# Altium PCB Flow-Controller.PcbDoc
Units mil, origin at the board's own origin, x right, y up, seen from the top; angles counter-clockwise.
Board outline 3346.46 x 3543.31 mil, 2 copper layers (Top Layer, Bottom Layer), stack 61.855 mil thick; 107 components, 78 nets, 319 pads, 143 vias.
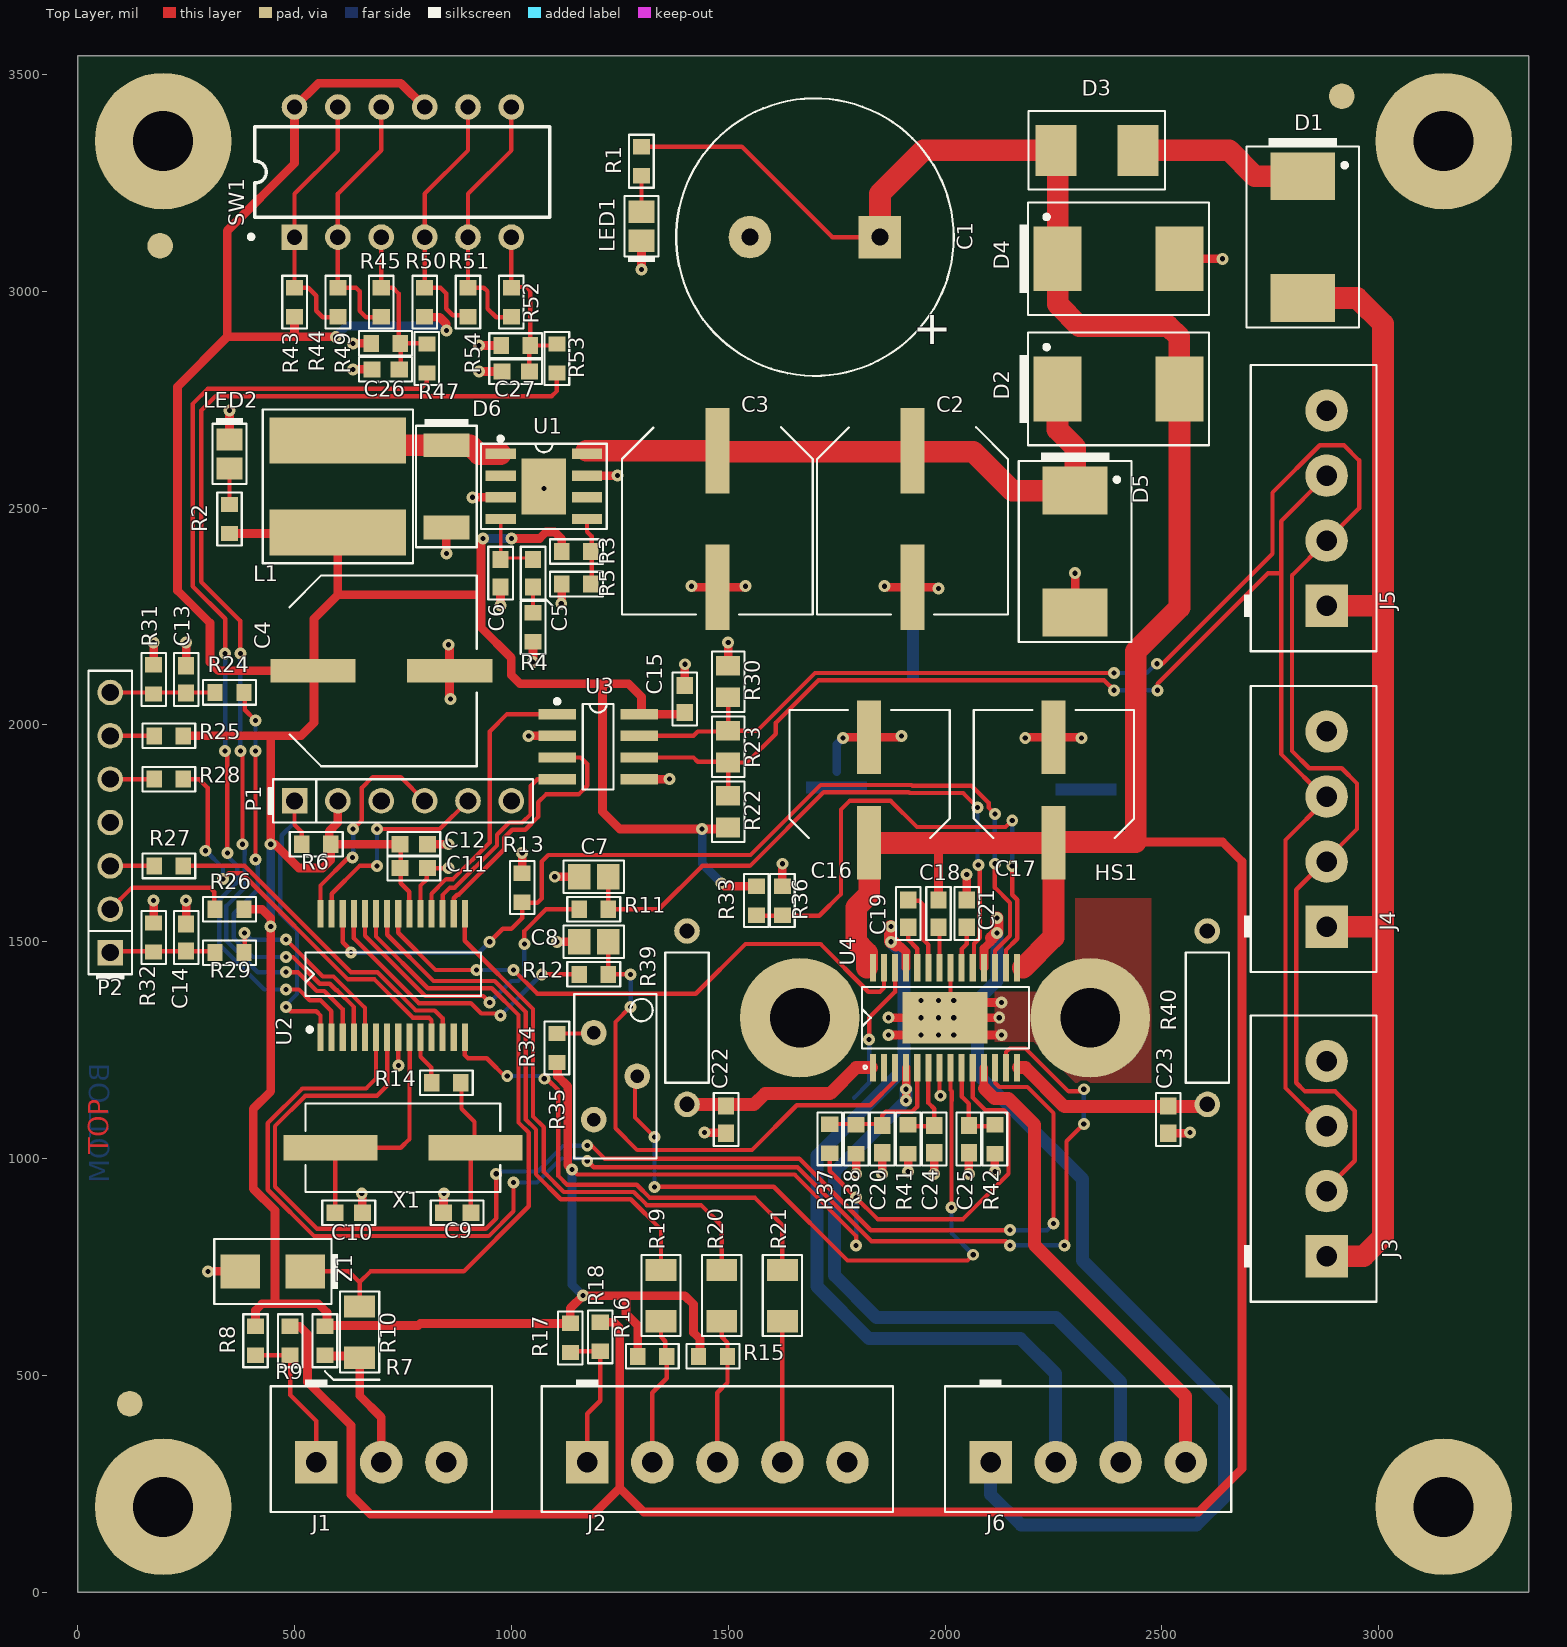
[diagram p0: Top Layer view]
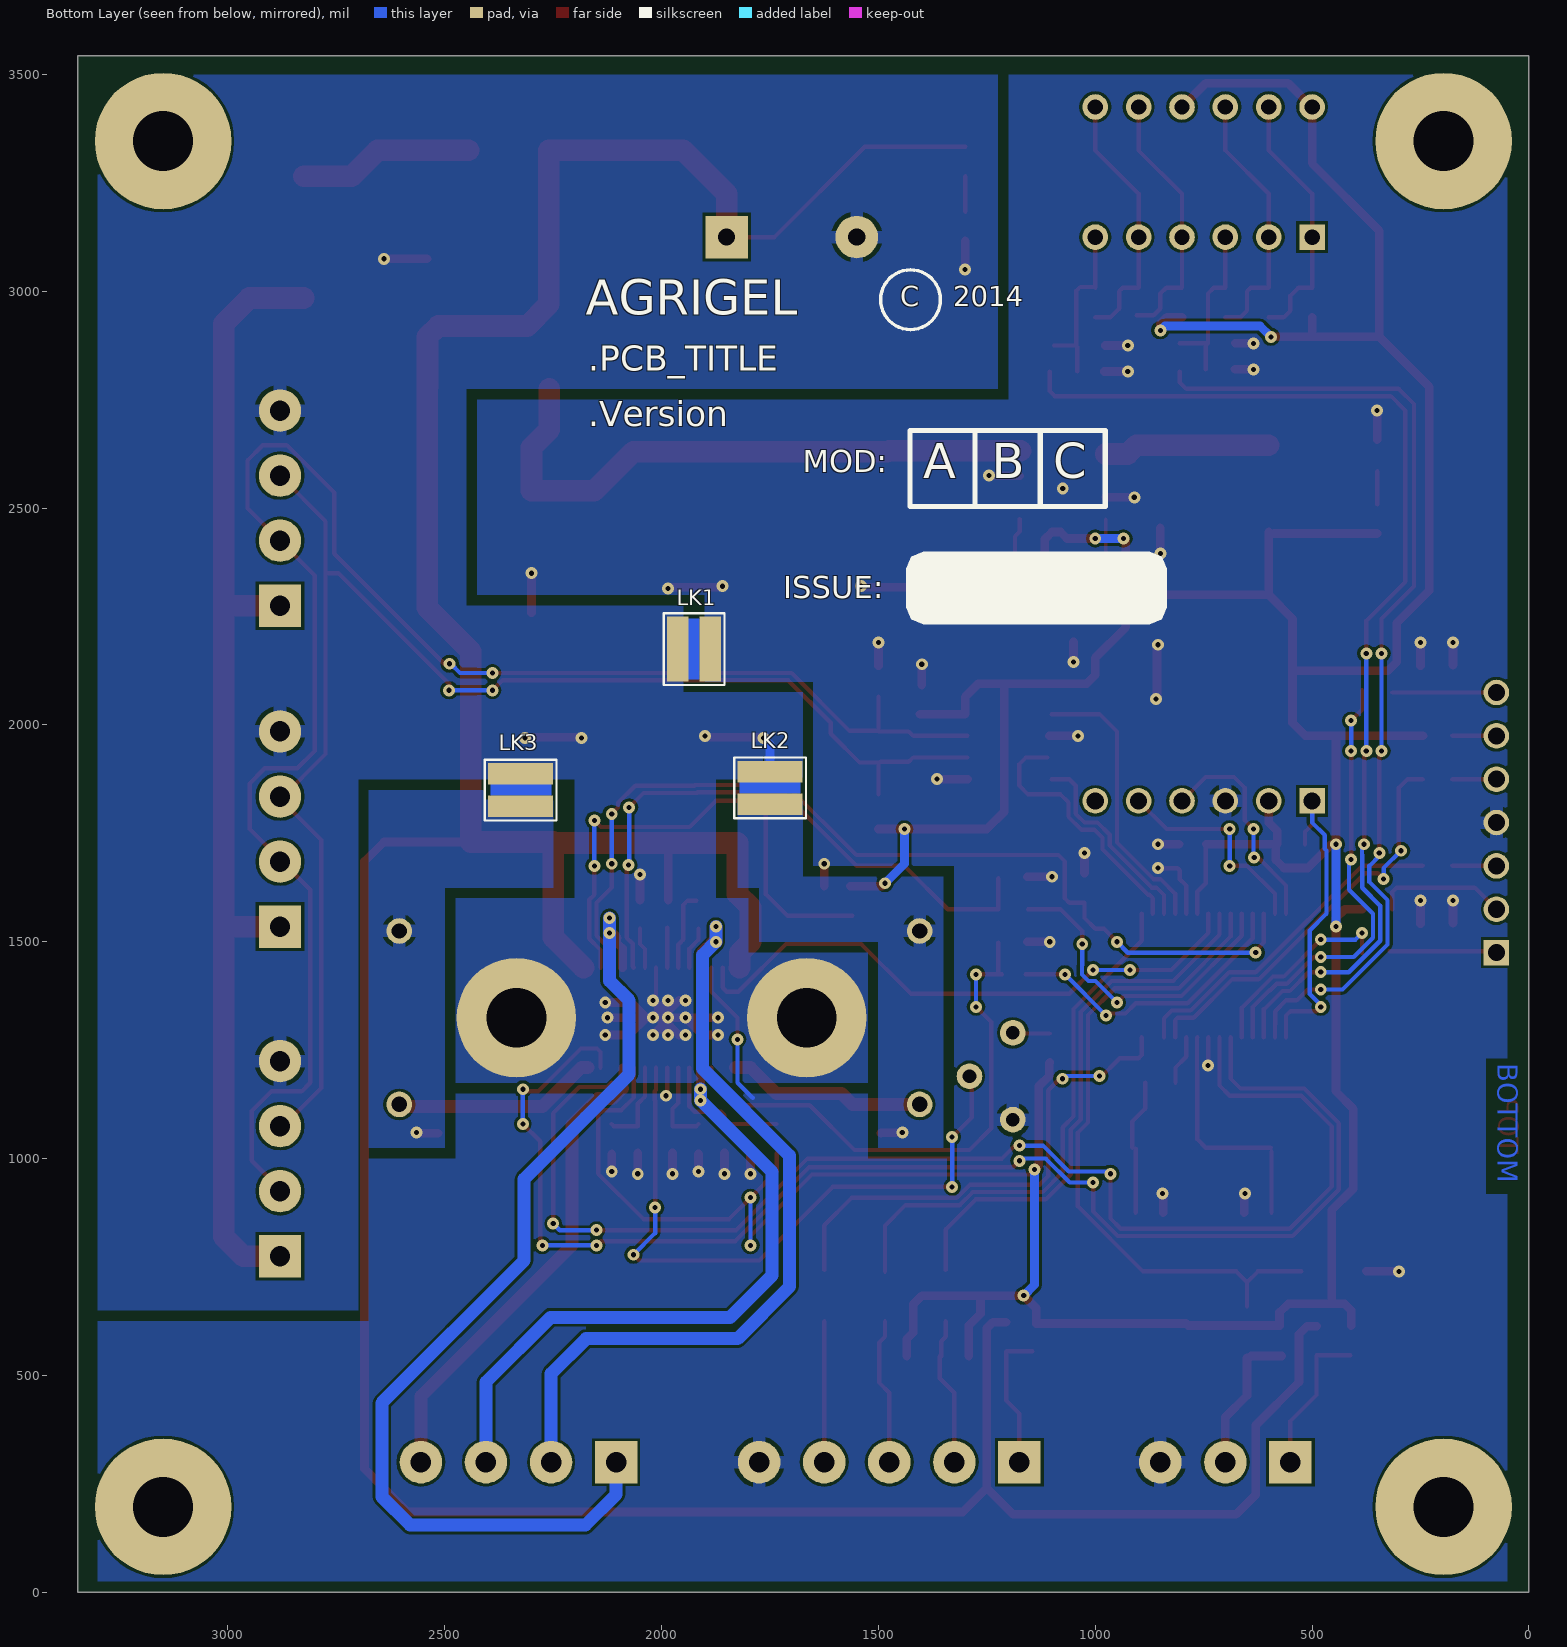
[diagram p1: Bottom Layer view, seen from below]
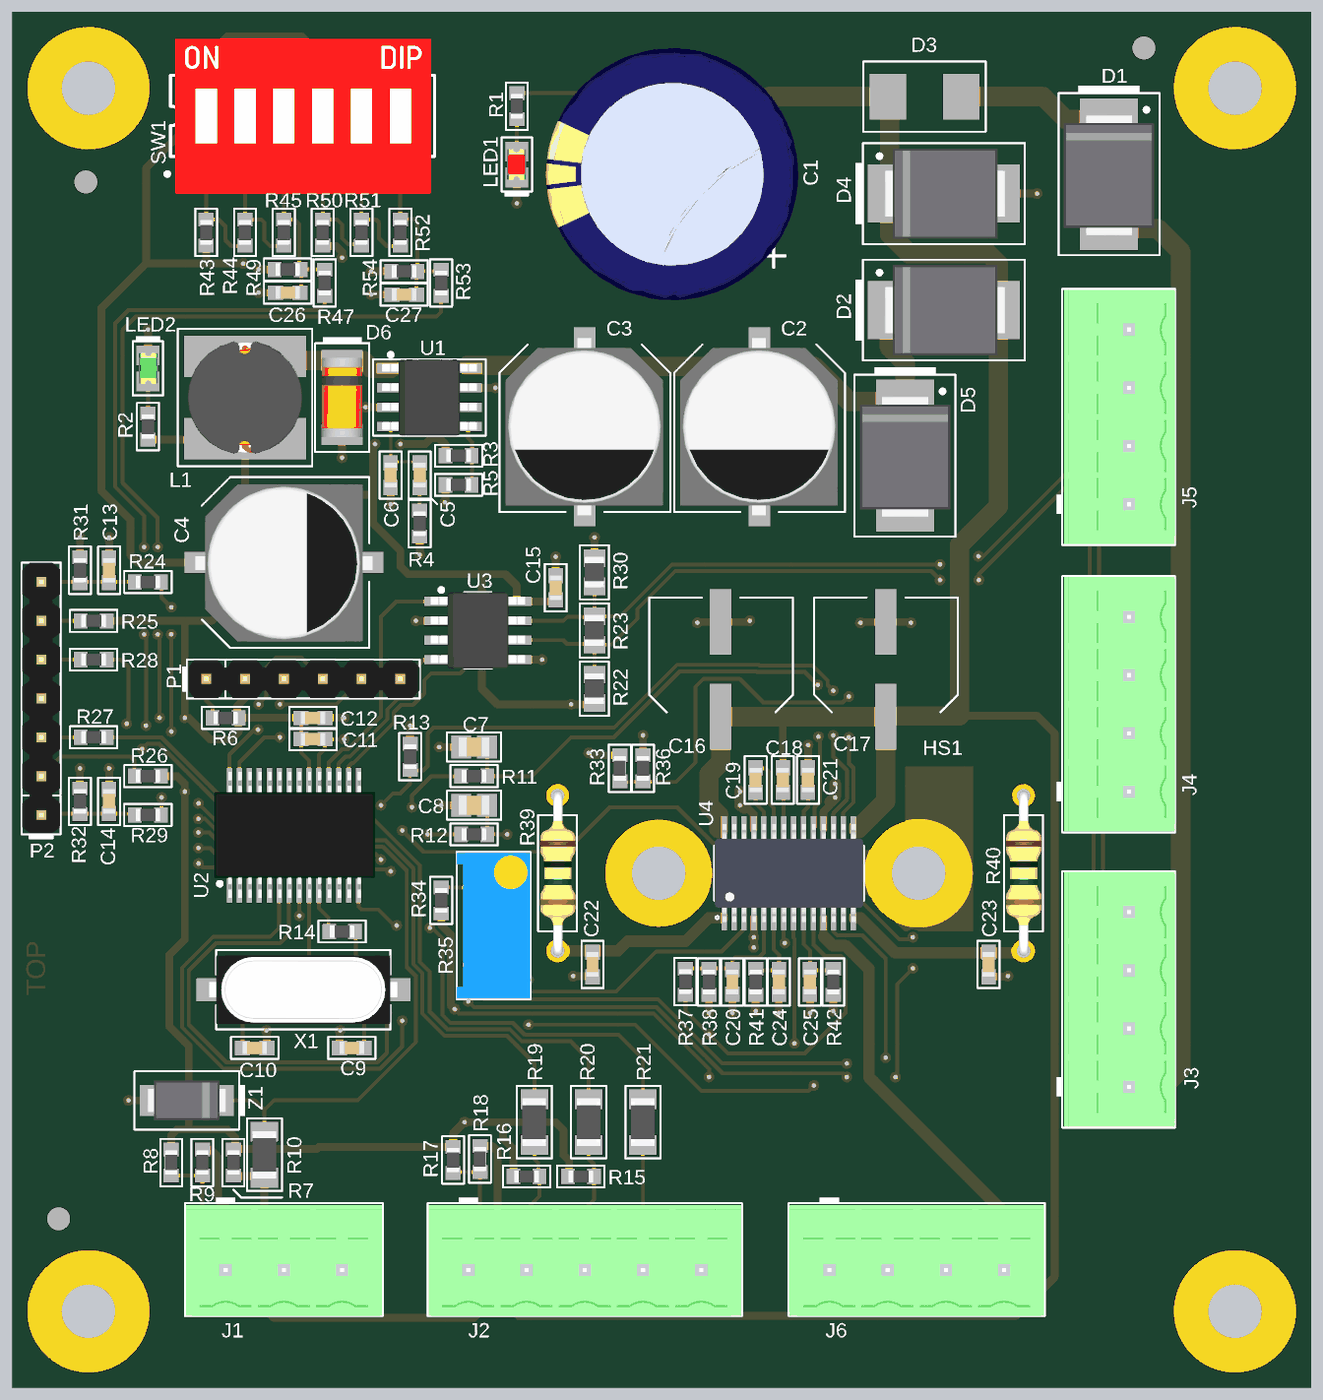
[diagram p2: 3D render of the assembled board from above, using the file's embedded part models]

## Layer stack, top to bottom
Top Layer: signal copper 1.4
Dielectric: prepreg 59.0551, FR-4, Dk 4.2
Bottom Layer: signal copper 1.4

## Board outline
0,0 3346.46,0 3346.46,3543.31 0,3543.31

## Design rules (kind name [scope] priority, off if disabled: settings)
Clearance [All] p1: gap=6.69
ComponentClearance [All] p1: gap=0 collisioncheckmode=3 verticalgap=1 showdistances=FALSE
FabricationTestPointUsage TestPointUsage [All] p1: valid=0 allowmultiple=FALSE
FabricationTestpoint Testpoint [All] p1: side=3 testpointundercomponent=TRUE minsize=40 maxsize=100 preferedsize=60 minholesize=0 maxholesize=40 preferedholesize=32 testpointgrid=1 allowsidetop=TRUE allowsidebottom=TRUE usegrid=TRUE gridtolerance=0.01
HoleSize [All] p1: absolutevalues=TRUE maxlimit=196.85 minlimit=9.84 maxpercent=80.000 minpercent=20.000
PlaneClearance [All] p1: clearance=19.68
PolygonConnect PolygonConnect_8 [All vs IsNamedPolygon('Top - GND1-HSK')] p1: connectstyle=Direct reliefconductorwidth=10 reliefentries=4 polygonreliefangle="90 Angle" airgapwidth=10
PolygonConnect PolygonConnect_7 [All vs IsNamedPolygon('Bot - GND1-HSK')] p2: connectstyle=Direct reliefconductorwidth=10 reliefentries=4 polygonreliefangle="90 Angle" airgapwidth=10
PolygonConnect PolygonConnect_6 [All vs IsNamedPolygon('Bot - GND4a') Or  IsNamedPolygon('Bot - GND2a') Or  IsNamedPolygon('Bot - GND3a')] p3: connectstyle=Direct reliefconductorwidth=10 reliefentries=4 polygonreliefangle="90 Angle" airgapwidth=10
PolygonConnect PolygonConnect_5 [All vs IsNamedPolygon('Bot - GND1a')] p4: connectstyle=Direct reliefconductorwidth=10 reliefentries=4 polygonreliefangle="90 Angle" airgapwidth=10
PolygonConnect PolygonConnectVia [All vs isvia] p5: connectstyle=Direct reliefconductorwidth=9.84 reliefentries=4 polygonreliefangle="90 Angle" airgapwidth=10
PolygonConnect PolygonConnect_4 [All vs IsNamedPolygon('Bot - GND2')] p6: connectstyle=Relief reliefconductorwidth=30 reliefentries=4 polygonreliefangle="90 Angle" airgapwidth=10
PolygonConnect PolygonConnect_3 [All vs IsNamedPolygon('Bot - GND1')] p7: connectstyle=Relief reliefconductorwidth=30 reliefentries=4 polygonreliefangle="90 Angle" airgapwidth=10
PolygonConnect PolygonConnect_2 [All vs IsNamedPolygon('Bot - GND4')] p8: connectstyle=Relief reliefconductorwidth=30 reliefentries=4 polygonreliefangle="90 Angle" airgapwidth=10
PolygonConnect PolygonConnect_1 [All vs IsNamedPolygon('Bot - GND3')] p9: connectstyle=Relief reliefconductorwidth=30 reliefentries=4 polygonreliefangle="90 Angle" airgapwidth=10
PolygonConnect [All] p10: connectstyle=Relief reliefconductorwidth=15.75 reliefentries=4 polygonreliefangle="90 Angle" airgapwidth=10
RoutingCorners [All] p1: cornerstyle=45-Degree minsetback=98.43 maxsetback=98.43
RoutingVias [All] p1: holewidth=11.81 width=27.56 viastyle="Through Hole" minholewidth=11.81 minwidth=27.56 maxholewidth=11.81 maxwidth=27.56
ShortCircuit ShortCircuit_LK1 [(InComponent('LK1'))] p1: allowed=TRUE
ShortCircuit ShortCircuit_LK2 [(InComponent('LK2'))] p2: allowed=TRUE
ShortCircuit ShortCircuit_LK3 [(InComponent('LK3'))] p3: allowed=TRUE
ShortCircuit [All] p4: allowed=FALSE
SilkToSolderMaskClearance SilkscreenOverComponentPads [IsPad] p1: minsilkscreentomaskgap=10 clearancetoexposedcopper=TRUE
SolderMaskExpansion [All] p1: expansion=1.97
Width "Width_High Power" [InNetClass('High Power')] p1: maxlimit=59.06 minlimit=19.68 preferedwidth=39.37
Width Width_Power [InNetClass('Power')] p2: maxlimit=39.37 minlimit=11.81 preferedwidth=19.68
Width [All] p3: maxlimit=78.74 minlimit=7.87 preferedwidth=7.87
20 further rules are at their usual default settings.

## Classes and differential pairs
component class Flow-Controller-2: C16 C17 C18 C19 C20 C21 C22 C23 C24 C25 C26 C27 HS1 J6 R33 R34 R35 R36 R37 R38 R39 R40 R41 R42 R43 R44 R45 R47 R49 R50 R51 R52 R53 R54 SW1 U4
component class Flow-Controller-1: C1 C2 C3 C4 C5 C6 C7 C8 C9 C10 C11 C12 C13 C14 C15 D1 D2 D3 D4 D5 D6 J1 J2 J3 J4 J5 L1 LED1 LED2 LK1 LK2 LK3 P1 P2 R1 R2 R3 R4 R5 R6 R7 R8 R9 R10 R11 R12 R13 R14 R15 R16 R17 R18 R19 R20 R21 R22 R23 R24 R25 R26 R27 R28 R29 R30 R31 R32 U1 U2 U3 X1 Z1

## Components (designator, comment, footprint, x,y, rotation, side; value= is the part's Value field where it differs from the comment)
C1 "CAP-EL_2200uF_35V_20%-YXF" EL-RAD-16X31.5 1700,3125 r180 top
C2 "100uF35V-20%-EEVFC" CAP-EL-SMD-10x10.5 1925,2475 r270 top
C3 "100uF35V-20%-EEVFC" CAP-EL-SMD-10x10.5 1475,2475 r270 top
C4 "470uF-35V-20%-LZ" CAP-EL-SMD-10x10.5 700,2125 r0 top
C5 "22nF_C0603_50V_10%_X7R" CAPC0603X85N 1050,2350 r270 top
C6 "220pF_C0603_50V_10%_NP0" CAPC0603X85N 975,2350 r270 top
C7 "DNF_C0805_50V_10%_X7R" CAPC0805X110N 1190,1650 r180 top
C8 "DNF_C0805_50V_10%_X7R" CAPC0805X110N 1190,1500 r180 top
C9 "33pF_C0603_50V_10%_NP0" CAPC0603X85N 875,875 r180 top
C10 "33pF_C0603_50V_10%_NP0" CAPC0603X85N 625,875 r0 top
C11 "10nF_C0603_50V_10%_X7R" CAPC0603X85N 775,1670 r0 top
C12 "100nF_C0603_50V_10%_X7R" CAPC0603X85N 775,1725 r0 top
C13 "10nF_C0603_50V_10%_X7R" CAPC0603X85N 250,2105 r90 top
C14 "10nF_C0603_50V_10%_X7R" CAPC0603X85N 250,1510 r90 top
C15 "100nF_C0603_50V_10%_X7R" CAPC0603X85N 1400,2060 r90 top
C16 "100uF-50V-20%-LZ" CAP-EL-SMD-8x10.5 1825,1850 r90 top
C17 "100uF-50V-20%-LZ" CAP-EL-SMD-8x10.5 2250,1850 r90 top
C18 "220nF_C0603_50V_10%_X7R" CAPC0603X85N 1985,1565 r270 top
C19 "220nF_C0603_50V_10%_X7R" CAPC0603X85N 1915,1565 r90 top
C20 "100nF_C0603_50V_10%_X7R" CAPC0603X85N 1855,1045 r270 top
C21 "220nF_C0603_50V_10%_X7R" CAPC0603X85N 2050,1565 r90 top
C22 "100nF_C0603_50V_10%_X7R" CAPC0603X85N 1495,1090 r270 top
C23 "100nF_C0603_50V_10%_X7R" CAPC0603X85N 2515,1090 r270 top
C24 "1.0nF_C0603_50V_10%_X7R" CAPC0603X85N 1975,1045 r270 top
C25 "1.0nF_C0603_50V_10%_X7R" CAPC0603X85N 2055,1045 r270 top
C26 "100nF_C0603_50V_10%_X7R" CAPC0603X85N 710,2820 r180 top
C27 "100nF_C0603_50V_10%_X7R" CAPC0603X85N 1010,2815 r180 top
D1 "ER3M" SMC 2825,3125 r270 top
D2 "ER3M" SMC 2400,2775 r0 top
D3 "0157003.DRT" LF-0157 2350,3325 r180 top
D4 "SMCJ26A" SMC 2400,3075 r0 top
D5 "SMCJ26A" SMC 2300,2400 r270 top
D6 "SMS2100" DO-213AB 850,2550 r270 top
HS1 "Heatsink-A3979" HEATSINK-A3979 2000,1325 r90 top
J1 "MCV 1,5/3-G-3.81" ECH381V-03P 700,300 r180 top
J2 "MCV 1,5/5-G-3.81" ECH381V-05P 1475,300 r180 top
J3 "MCV 1,5/4-G-3.81" ECH381V-04P 2880,1000 r270 top
J4 "MCV 1,5/4-G-3.81" ECH381V-04P 2880,1760 r270 top
J5 "MCV 1,5/4-G-3.81" ECH381V-04P 2880,2500 r270 top
J6 "MCV 1,5/4-G-3.81" ECH381V-04P 2330,300 r180 top
L1 "SDR0805-330K" SDR0805 600,2550 r270 top
LED1 "RED_0805_SMD" LED0805-Red 1300,3150 r90 top
LED2 "GREEN_0805_SMD" LED0805-Green 350,2625 r270 top
LK1 "Link-SMD-10A-Closed" SLINK-10A-C 1925,2175 r180 bottom
LK2 "Link-SMD-10A-Closed" SLINK-10A-C 1750,1855 r270 bottom
LK3 "Link-SMD-10A-Closed" SLINK-10A-C 2325,1850 r270 bottom
P1 "SIL6P-2.54" SIL6P-2.54 750,1825 r0 top
P2 "SIL7P-2.54" SIL7P-2.54 75,1775 r90 top
R1 "10K_R0603_1%" RESC0603X60N 1300,3300 r270 top
R2 "470R_R0603_1%" RESC0603X60N 350,2475 r90 top
R3 "10K_R0603_1%" RESC0603X60N 1150,2400 r0 top
R4 "4K7_R0603_1%" RESC0603X60N 1050,2225 r270 top
R5 "3K3_R0603_1%" RESC0603X60N 1150,2325 r180 top
R6 "10K_R0603_1%" RESC0603X60N 550,1725 r180 top
R7 "10K_R0603_1%" RESC0603X60N 570,580 r270 top
R8 "0R_R0603_1%" RESC0603X60N 410,580 r270 top
R9 "DNP_R0603_1%" RESC0603X60N 490,580 r270 top
R10 "100R_R1206_1%" RESC1206X71N 650,600 r270 top
R11 "1K_R0603_1%" RESC0603X60N 1190,1575 r0 top
R12 "1K_R0603_1%" RESC0603X60N 1190,1425 r0 top
R13 "2K2_R0603_1%" RESC0603X60N 1025,1625 r90 top
R14 "0R_R0603_1%" RESC0603X60N 850,1175 r180 top
R15 "1K_R0603_1%" RESC0603X60N 1465,544.06 r0 top
R16 "10K_R0603_1%" RESC0603X60N 1325,544.06 r0 top
R17 "0R_R0603_1%" RESC0603X60N 1135.94,586.54 r270 top
R18 "DNP_R0603_1%" RESC0603X60N 1205,589.06 r270 top
R19 "100R_R1206_1%" RESC1206X71N 1345,684.06 r270 top
R20 "100R_R1206_1%" RESC1206X71N 1485,684.06 r270 top
R21 "100R_R1206_1%" RESC1206X71N 1625,684.06 r270 top
R22 "DNP_R0805_1%" RESC0805X65N 1500,1800 r90 top
R23 "DNP_R0805_1%" RESC0805X65N 1500,1950 r90 top
R24 "1K_R0603_1%" RESC0603X60N 350,2075 r180 top
R25 "1K8_R0603_1%" RESC0603X60N 210,1975 r180 top
R26 "1K_R0603_1%" RESC0603X60N 350,1575 r180 top
R27 "470R_R0603_1%" RESC0603X60N 210,1675 r180 top
R28 "470R_R0603_1%" RESC0603X60N 210,1875 r180 top
R29 "1K_R0603_1%" RESC0603X60N 350,1475 r180 top
R30 "DNP_R0805_1%" RESC0805X65N 1500,2100 r90 top
R31 "1K_R0603_1%" RESC0603X60N 175,2105 r90 top
R32 "1K_R0603_1%" RESC0603X60N 175,1510 r90 top
R33 "DNP_R0603_1%" RESC0603X60N 1565,1595 r270 top
R34 "2K2_R0603_1%" RESC0603X60N 1105,1255 r90 top
R35 "3296Y-1-103" 3296Y-THP 1240,1190 r270 top
R36 "1K_R0603_1%" RESC0603X60N 1625,1595 r90 top
R37 "4K7_R0603_1%" RESC0603X60N 1734.25,1045.75 r90 top
R38 "4K7_R0603_1%" RESC0603X60N 1795,1045 r270 top
R39 "0R27-0.250W-5%" RES-0.250W 1405,1325 r270 top
R40 "0R27-0.250W-5%" RES-0.250W 2605,1325 r270 top
R41 "33K_R0603_1%" RESC0603X60N 1915,1045 r270 top
R42 "33K_R0603_1%" RESC0603X60N 2115,1045 r270 top
R43 "3K9_R0603_1%" RESC0603X60N 500,2975 r90 top
R44 "2K2_R0603_1%" RESC0603X60N 600,2975 r90 top
R45 "1K_R0603_1%" RESC0603X60N 700,2975 r90 top
R47 "1K_R0603_1%" RESC0603X60N 805,2845 r90 top
R49 "5K6_R0603_1%" RESC0603X60N 710,2880 r180 top
R50 "3K9_R0603_1%" RESC0603X60N 800,2975 r90 top
R51 "2K2_R0603_1%" RESC0603X60N 900,2975 r90 top
R52 "1K_R0603_1%" RESC0603X60N 1000,2975 r90 top
R53 "1K_R0603_1%" RESC0603X60N 1105,2845 r90 top
R54 "5K6_R0603_1%" RESC0603X60N 1010,2875 r180 top
SW1 "DS-06" DIP-SW6 750,3275 r90 top
U1 "L5973D-HSOP8" HSOP8 1075,2550 r0 top
U2 "PIC18F25K22-I/SS" SSOP28 725,1425 r90 top
U3 "DS75176BM" SO8 1200,1950 r0 top
U4 "A3979SLPTR" TSSOP28-4.4-LP 2000,1325 r90 top
X1 "XTAL_11.0592MHz_STCX15" XT-HEX15 750,1025 r180 top
Z1 "1SMA5918BT3" SMA 450,740 r180 top

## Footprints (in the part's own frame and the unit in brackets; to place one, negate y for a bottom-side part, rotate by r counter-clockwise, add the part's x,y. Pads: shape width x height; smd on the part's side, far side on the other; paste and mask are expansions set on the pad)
3296Y-THP [mm] "Variable Resistor, Bourns, Straight THP"
  round 1.5 hole 0.8 paste+0 mask+0.05: 1(-2.54,-1.27) 2(0,1.27) 3(2.54,-1.27)
  silkscreen extent -4.83,-2.41 4.83,2.41, body extent -4.76,-2.43 4.77,2.4, height 11.55
CAP-EL-SMD-8x10.5 [mm] "CAP El SMD 8.0x10.5mm"
  rect 4.3x1.4 smd mask+0.025: 1(-3.1,0) 2(3.1,0)
  silkscreen extent -2.81,-4.73 4.68,4.67, body extent -4.18,-4.2 4.18,4.15, height 10.5
CAP-EL-SMD-10x10.5 [mm] "CAP El SMD 10.0x10.0mm"
  rect 5x1.4 smd mask+0.025: 1(-4,0) 2(4,0)
  silkscreen extent -5.37,-5.59 5.59,5.59, body extent -5.8,-5.17 5.8,5.13, height 10.21
CAPC0603X85N [mm] "Chip Capacitor, 0603, 2-Leads, Body 1.6x0.8mm, IPC Medium Density"
  rect 1x0.95 smd paste+0 mask+0.05: 1(-0.8,0) 2(0.8,0)
  silkscreen extent -1.55,-0.72 1.55,0.72, body extent -0.8,-0.4 0.8,0.4, height 0.8
CAPC0805X110N [mm] "Chip Capacitor, 0805, 2-Leads, Body 2.0x1.3mm, IPC Medium Density"
  rect 1.3x1.5 smd paste+0 mask+0.05: 1(-0.85,0) 2(0.85,0)
  silkscreen extent -1.77,-0.95 1.77,0.95, body extent -1,-0.63 1,0.63, height 1.22
DIP-SW6 [mm] "DIP Switch 6 Way"
  rect 1.5x1.5 hole 0.9: 1(-3.81,6.35)
  round 1.5 hole 0.9: 2(-3.81,3.81) 3(-3.81,1.27) 4(-3.81,-1.27) 5(-3.81,-3.81) 6(-3.81,-6.35) 7(3.81,-6.35) 8(3.81,-3.81) 9(3.81,-1.27) 10(3.81,1.27) 11(3.81,3.81) 12(3.81,6.35)
  silkscreen extent -3.92,-8.59 2.67,9.02, body extent -5.08,-8.38 5.08,8.38, height 6.9
DO-213AB [mil] "DO-213AB 5.0x2.5mm"
  rect 55x106 smd mask+1: 1(-95,0) 2(95,0)
  silkscreen extent -155,-70 140,70, body extent -102,-53 102,53, height 106
ECH381V-03P [mil] "ECH381V-03P 12.22x7.0mm"
  rect 98x98 hole 47.24: 1(150,0)
  round 98 hole 47.24: 2(0,0) 3(-150,0)
  silkscreen extent -255,-190 255,115, body extent -252,-170 252,115, height 362
ECH381V-04P [mil] "ECH381V-04P 19.84x7.0mm"
  rect 98x98 hole 47.24: 1(225,0)
  round 98 hole 47.24: 2(75,0) 3(-75,0) 4(-225,0)
  silkscreen extent -330,-190 330,115, body extent -327,-170 327,115, height 362
ECH381V-05P [mil] "ECH381V-05P 23.65x7.0mm"
  rect 98x98 hole 47.24: 1(300,0)
  round 98 hole 47.24: 2(150,0) 3(0,0) 4(-150,0) 5(-300,0)
  silkscreen extent -405,-190 405,115, body extent -402,-170 402,115, height 362
EL-RAD-16X31.5 [mil] "Capacitor, Electrolytic, THP, Radial, Dia 16mm, Pitch 7.5mm"
  rect 98x98 hole 39.37: 1(-150,0)
  round 98 hole 39.37: 2(150,0)
  silkscreen extent -320,-320 320,320, body extent -325,-325 325,325, height 1266
HEATSINK-A3979 [mm] "HEATSINK A3979 25.0X15.0mm"
  round 7 hole 3.5: 1(0,8.5) 2(0,-8.5)
  body extent -7.5,-11.5 7.5,11.5, height 13.2
HSOP8 [mil] "HSOP 8-Leads, Body 5.0x4.0mm, Pitch 1.27mm"
  rect 70x24 smd paste+0 mask+1.97: 1(-99.49,75) 2(-99.49,25) 3(-99.49,-25) 4(-99.49,-75) 5(99.49,-75) 6(99.49,-25) 7(99.49,25) 8(99.49,75)
  rect 102.36x129.92 smd mask+1: 9(0,0)
  silkscreen extent -145,-98 145,115, body extent -122,-98 122,98, height 70
LED0805-Green [mm] "LED, 0805, 2-Leads, Body 2.0x1.3mm, IPC Medium Density"
  rect 1.3x1.5 smd paste+0 mask+0.025: 1(-0.85,0) 2(0.85,0)
  silkscreen extent -2.1,-1 1.77,0.99, body extent -1.01,-0.6 1.01,0.65, height 1.2
LED0805-Red [mm] "LED, 0805, 2-Leads, Body 2.0x1.3mm, IPC Medium Density"
  rect 1.3x1.5 smd paste+0 mask+0.025: 1(-0.85,0) 2(0.85,0)
  silkscreen extent -2.1,-1 1.77,0.99, body extent -1.01,-0.6 1.01,0.65, height 1.2
LF-0157 [mm] "Fuse 0157 6.5x3.7mm"
  rect 2.4x3 smd mask+0.025: 1(-2.4,0) 2(2.4,0)
  silkscreen extent -4,-2.3 4,2.3, body extent -3.4,-1.9 3.4,1.9, height 3.9
RES-0.250W [mil] "Res 0.25W 7.6x2.3mm"
  round 59 hole 35.43: 1(-200,0) 2(200,0)
  silkscreen extent -150,-50 150,50, body extent -212,-45 212,46, height 96
RESC0603X60N [mm] "Chip Resistor, 0603, 2-Leads, Body 1.6x0.8mm, IPC Medium Density"
  rect 0.9x1 smd paste+0 mask+0.05: 1(-0.85,0) 2(0.85,0)
  silkscreen extent -1.55,-0.72 1.55,0.72, body extent -0.8,-0.4 0.8,0.4, height 0.37
RESC0805X65N [mm] "Chip Resistor, 0805, 2-Leads, Body 2.0x1.3mm, IPC Medium Density"
  rect 1.15x1.4 smd paste+0 mask+0.05: 1(-0.925,0) 2(0.925,0)
  silkscreen extent -1.77,-0.95 1.77,0.95, body extent -0.99,-0.62 1.01,0.63, height 0.47
RESC1206X71N [mm] "Chip Resistor, 1206, 2-Leads, Body 3.2x1.6mm, IPC Medium Density"
  rect 1.3x1.8 smd paste+0 mask+0.05: 1(-1.5,0) 2(1.5,0)
  silkscreen extent -2.37,-1.15 2.37,1.15, body extent -1.55,-0.78 1.55,0.77, height 0.47
SDR0805 [mm] "SDR0805 7.8x7.8mm"
  rect 2.7x8 smd mask+0.025: 1(-2.7,0) 2(2.7,0)
  silkscreen extent -4.5,-4.4 4.5,4.4, body extent -3.68,-3.75 3.68,3.75, height 5.05
SIL6P-2.54 [mil] "SIL Strip 2.54mm"
  rect 59x59 hole 39.37: 1(-250,0)
  round 59 hole 39.37: 2(-150,0) 3(-50,0) 4(50,0) 5(150,0) 6(250,0)
  silkscreen extent -310,-50 300,50, body extent -296,-49 300,49, height 323
SIL7P-2.54 [mil] "SIL Strip 2.54mm"
  rect 59x59 hole 39.37: 1(-300,0)
  round 59 hole 39.37: 2(-200,0) 3(-100,0) 4(0,0) 5(100,0) 6(200,0) 7(300,0)
  silkscreen extent -360,-50 350,50, body extent -346,-49 350,49, height 323
SLINK-10A-C [mil] "Solder Link 10Amp Closed"
  rect 50x149.61 smd mask+0.98: 1(-37.5,0) 2(37.5,0)
  Top Layer region: -15,70.67 12.56,70.67 12.56,-70 -15,-70
  silkscreen extent -70,-83 70,83
SMA [mil] "SMA 5.6x2.95mm"
  rect 91x79 smd mask+0.98: 1(-75,0.08) 2(75,0.08)
  silkscreen extent -150,-75 135,75, body extent -102,-51 102,51, height 91
SMC [mm] "Molded Diode, 2-Leads, Body 6.9x5.8mm, IPC Medium Density"
  rect 2.8x3.8 smd mask+0.025: 1(-3.57,0) 2(3.57,0)
  silkscreen extent -5.8,-3.3 5.3,3.3, body extent -3.9,-2.95 4.05,2.95, height 2.3
SO8 [mm] "SOIC, 8-Leads, Body 5.0x4.0mm (max), Pitch 1.27mm, IPC Medium Density"
  rect 2.2x0.6 smd paste+0 mask+0.05: 1(-2.4,1.905) 2(-2.4,0.635) 3(-2.4,-0.635) 4(-2.4,-1.905) 5(2.4,-1.905) 6(2.4,-0.635) 7(2.4,0.635) 8(2.4,1.905)
  silkscreen extent -2.52,-2.5 0.9,2.77, body extent -3.1,-2.5 3.1,2.5, height 1.78
SSOP28 [mil] "SSOP 28 0.65mm 5.3x10.2mm"
  rect 63x14 smd mask+1: 1(-145,165) 2(-145,139.41) 3(-145,113.82) 4(-145,88.23) 5(-145,62.64) 6(-145,37.05) 7(-145,11.46) 8(-145,-14.13) 9(-145,-39.72) 10(-145,-65.31) 11(-145,-90.9) 12(-145,-116.49) 13(-145,-142.08) 14(-145,-167.67) 15(140,-167.67) 16(140,-142.08) 17(140,-116.49) 18(140,-90.9) 19(140,-65.31) 20(140,-39.72) 21(140,-14.13) 22(140,11.46) 23(140,37.05) 24(140,62.64) 25(140,88.23) 26(140,113.82) 27(140,139.41) 28(140,165)
  silkscreen extent -132,-205 50,200, body extent -163,-210 160,204, height 76
TSSOP28-4.4-LP [mil] "TSSOP28 LP 4.4x9.7mm"
  rect 63x14 smd mask+0.98: 1(-115.16,166.34) 2(-115.16,140.75) 3(-115.16,115.16) 4(-115.16,89.57) 5(-115.16,63.98) 6(-115.16,38.39) 7(-115.16,12.8) 8(-115.16,-12.79) 9(-115.16,-38.38) 10(-115.16,-63.97) 11(-115.16,-89.56) 12(-115.16,-115.15) 13(-115.16,-140.74) 14(-115.16,-166.33) 15(114.84,-166.33) 16(114.84,-140.74) 17(114.84,-115.15) 18(114.84,-89.56) 19(114.84,-63.97) 20(114.84,-38.38) 21(114.84,-12.79) 22(114.84,12.8) 23(114.84,38.39) 24(114.84,63.98) 25(114.84,89.57) 26(114.84,115.16) 27(114.84,140.75) 28(114.84,166.34)
  rect 118.11x196.85 smd mask+1: 29(0,0)
  silkscreen extent -118,-194 71,191, body extent -126,-192 126,190, height 38
XT-HEX15 [mm] "XTAL-HEX15, 2-Leads, Body 11.1x4.83mm (max), Pitch 4.3mm"
  rect 5.5x1.5 smd paste+0 mask+0.025: 1(-4.25,0) 2(4.25,0)
  silkscreen extent -5.7,-2.6 5.7,2.6, body extent -6.15,-2.25 6.15,2.25, height 5.18

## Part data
C1: library part 2200uF_35V_20%_V-YXF, "Cap Electrolytic THP Radial - Low Imp"
C2 C3: library part 100uF-35V-20%-EEVFC_V, "Cap Electrolytic SMD Low Imp"
C4: library part 470uF-35V-20%-LZ_V, "Cap Electrolytic SMD Low Imp"
C5: library part 22nF_0603N_50V_10%_X7R_V, "Cap Ceramic X7R"
C6: library part 220pF_0603N_50V_10%_NP0_V, "Cap Ceramic NP0"
C7 C8: library part DNF_0805N_50V_10%_X7R_V, "Do not Fit - Cap Ceramic X7R"
C9 C10: library part 33pF_0603N_50V_10%_NP0_V, "Cap Ceramic NP0"
C11 C13 C14: library part 10nF_0603N_50V_10%_X7R_V, "Cap Ceramic X7R"
C12 C15 C20 C22 C23 C26 C27: library part 100nF_0603N_50V_10%_X7R_V, "Cap Ceramic X7R"
C16 C17: library part 100uF-50V-20%-LZ_V, "Cap Electrolytic SMD Low Imp"
C18 C21: library part 220nF_0603N_50V_10%_X7R_V, "Cap Ceramic X7R"
C19: library part 220nF_0603N_50V_10%_X7R_H, "Cap Ceramic X7R"
C24 C25: library part 1nF_0603N_50V_10%_X7R_V, "Cap Ceramic X7R"
D1 D2: library part ER3M_SMC_H, "Diode Rectifier (1000V 3A)"
D3: library part FUSE_0157003.DRT_3.0AMP, "Fuse Clip and Nano Fuse"
D4 D5: library part SMCJ26A_V, "TVS 1500W SMC"
D6: library part SMS2100_V, "Diode Schottky Rectifier 2Amp 100V"
HS1: "Heatsink Vertical PCB Mount A3979"
J1 J2 J3 J4 J5 J6: "Header Pluggable 3.81mm Vertical"
L1: library part 33uH_SDR0805_H, "Inductor Power"
LED1: library part RED_0805_SMD_V, "LED SMD 0805 Red"
LED2: library part GREEN_0805_SMD_V, "LED SMD 0805 Green"
LK1 LK2 LK3: "Link SMD Closed 10Amp"
P1 P2: "Header SIL Male THP, 2.54mm Pitch"
R1 R3 R6 R7 R16: library part 10K_0603_V, "Resistor Chip SMD"
R2 R27 R28: library part 470R_0603_V, "Resistor Chip SMD"
R4 R37 R38: library part 4K7_0603_V, "Resistor Chip SMD"
R5: library part 3K3_0603_V, "Resistor Chip SMD"
R8 R17: library part 0R_0603_V, "Resistor Chip SMD"
R9 R18 R33: library part DNP_0603_V, "Resistor Chip SMD"
R10 R19 R20 R21: library part 100R_1206_H, "Resistor Chip SMD"
R11 R12 R24 R29 R47 R53: library part 1K_0603_H, "Resistor Chip SMD"
R13 R34 R44 R51: library part 2K2_0603_V, "Resistor Chip SMD"
R14: library part 0R_0603_H, "Resistor Chip SMD"
R15 R26 R31 R32 R36 R45 R52: library part 1K_0603_V, "Resistor Chip SMD"
R22 R23 R30: library part DNP_0805_V, "Resistor Chip SMD"
R25: library part 1K8_0603_V, "Resistor Chip SMD"
R35: library part 10K_3296Y-1-103_THP_V, "Variable Resistor THP"
R39 R40: library part 0R27-0.250W-5%_V, "Resistor Metal Film"
R41 R42: library part 33K_0603_V, "Resistor Chip SMD"
R43 R50: library part 3K9_0603_V, "Resistor Chip SMD"
R49 R54: library part 5K6_0603_V, "Resistor Chip SMD"
SW1: library part SW-DIP-DS-06, "DIP Slide Switch"
U1: "IC Switching Regulator 2.5A"
U2: library part PIC18F25K22-I/SS_SSOP28, "IC Microcontroller 8-Bit"
U3: library part DS75176BM_SO8, "IC 3.3V RS-485 Drivers and Receivers"
U4: library part A3979SLPTR_TSSOP28, "IC Microstepping DMOS Driver"
X1: "Crystal - HEX15"
Z1: library part 1SMA5918BT3_X, "Zener Diode 1.5W"

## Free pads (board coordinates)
  round 314.96 hole 137.8: 0(196.85,3346.46) 1(3149.61,3346.46) 2(196.85,196.85) 3(3149.61,196.85)
  round 59.06 smd paste+0 mask+1.97: 1(120,435) 1(190,3105) 1(2915,3450)

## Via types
v1: diameter 27.56, hole 11.81, Top Layer to Bottom Layer, tented both sides, 143 vias

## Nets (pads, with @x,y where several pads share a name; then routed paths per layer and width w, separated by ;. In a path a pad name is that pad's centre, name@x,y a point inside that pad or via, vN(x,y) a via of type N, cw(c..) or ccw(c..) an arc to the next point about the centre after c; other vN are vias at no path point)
485+: J3.3 J4.3 J5.3 R22.2 R23.1 U3.6 | length 3447.4
  Top Layer w10: U3.6 1420,1925 1430,1915 R23.1@1495,1915 ; R22.2@1500,1840 R23.1 1543.58,1913.58 1610,1980 1610,2005 1708.31,2103.31 2366.69,2103.31 v1(2390,2080) ; v1(2490,2080) 2490,2095.11 2744.89,2350 2775,2350 ; J3.3@2879.02,1068.9 2785,1162.91 2785,1734.88 2879.02,1828.9 2775,1932.91 2775,2350 ; J5.3 2775,2470 2775,2350
  Bottom Layer w10: v1(2390,2080) v1(2490,2080)
485-: J3.2 J4.2 J5.2 R23.2 R30.1 U3.7 | length 4150.8
  Top Layer w10: U3.7 1420,1975 1430,1985 R23.2@1500,1985 ; R30.1@1500,2065 R30.1 R23.2 1566.42,1986.42 1700,2120 v1(2390,2120) ; v1(2488.79,2141.21) 2501.21,2141.21 2755,2395 2755,2535.83 2864.17,2645 2920,2645 2954.92,2610.08 2954.92,2499.92 J5.2 ; J5.2@2879.02,2431.1 2879.02,2424.02 2800,2345 2800,1940 2840,1900 2915,1900 2950,1865 2950,1760 2810,1620 2810,1175 2830,1155 2900,1155 2945,1110 2945,995 J3.2@2880,930
  Bottom Layer w10: v1(2390,2120) 2465,2120 2486.21,2141.21 v1(2488.79,2141.21)
+5V: C4.1 C11.1 C12.1 C15.1 L1.2 P1.2 R2.1 R3.1 R6.1 R7.1 R8.1 R15.1 R16.1 R17.1 R22.1 R25.1 R26.1 R33.1 R34.1 R37.1 R43.1 R50.1 SW1.9 SW1.12 U2.20 U3.8 U4.10 | length 11617.8
  Top Layer w10: C12.1@745,1720 745,1635 764.72,1615.28 U2.20 ; v1(1140,975) 1151.69,963.31 1653.09,963.31 1795,821.39 v1(1795,800) ; R37.1 1734.25,970.75 v1(1795,910) 1844.53,860.47 2041.5,860.47 2146.38,965.35 2146.38,1101.02 2135.79,1111.61 2093.39,1111.61 2063.97,1141.03 U4.10
  Top Layer w20: R25.1 445,1975 ; R2.1 L1.2@588.46,2441.54 ; R26.1@385,1575 425,1575 445,1555 v1(445,1535) 445,1155 405,1115 405,930.71 455,880.71 455,665 ; R8.1@410,615 410,650 425,665 455,665 ; R43.1@500,2940 500,2895 ; C4.1@545,2125 545,2005 515,1975 445,1975 ; v1(595,2895) 500,2895 ; P1.2 600,1775 580,1755 580,1725 R6.1 ; L1.2@600,2445 L1.2 600,2300 ; C12.1 R6.1 ; R50.1@800,2940 835,2940 850,2925 v1(850,2910) ; SW1.9 745,3480 555,3480 SW1.12 500,3295 345,3140 345,2895 ; v1(935,2430) 930,2425 930,2300 ; v1(1000,2430) 1065,2430 1080,2445 1100,2445 1116.54,2428.46 R3.1 ; R34.1 1106.4,1220.13 1106.4,1190.3 1130.08,1166.62 1130.08,984.92 v1(1140,975) ; R16.1 1291.54,615.12 1264.49,642.16 1264.49,684.06 ; C15.1@1405,2025 1300,2025 1300,2065 1270,2095 1210,2095 ; R15.1@1435,544.06 1435,584.06 1420,599.06 1420,664.06 1400,684.06 1264.49,684.06 ; v1(1485,1635) 1491.54,1628.46 R33.1 ; R22.1@1500,1760 v1(1440,1760) 1250,1760 1210,1800 1210,2095 ; 345,2895 500,2895 ; 345,2895 230,2780 230,2310 305,2235 305,2145 325,2125 C4.1 545,2127.48 545,2245 600,2300 ; 445,1975 v1(445,1725) 455,1725 510,1670 565,1670 583.46,1688.46 R6.1 ; 455,665 555,665 575,645 575,615 785,615 790,620 R17.1 1135.94,655 v1(1165,684.06) 1264.49,684.06 ; 600,2300 930,2300 ; 930,2300 930,2225 1000,2155 1000,2115 1020,2095 1210,2095
  Bottom Layer w10: v1(1795,800) v1(1795,910)
  Bottom Layer w20: v1(445,1535) v1(445,1725) ; v1(595,2895) 620,2920 840,2920 v1(850,2910) ; v1(935,2430) v1(1000,2430) ; v1(1140,975) 1140,709.06 v1(1165,684.06) ; v1(1440,1760) 1440,1680 v1(1485,1635)
BLACK: J6.1 U4.18 | length 2475.9
  Top Layer w10: U4.18 2089.56,1489.56 2105,1505 v1(2120,1520)
  Top Layer w20: U4.18@2090,1440 2090,1484.65 2105,1499.65 2105,1505
  Top Layer w30: 2107.09,1508.81 2120,1521.73 v1(2120,1555)
  Bottom Layer w30: J6.1 2105,225.47 2175.47,155 2580,155 2645,220 2645,436.85 2317.32,764.53 2317.32,952.52 2175,1094.84 2075,1194.84 2075,1365 2120,1410 v1(2120,1520) v1(2120,1555)
BLUE: J6.2 U4.25 | length 1948.1
  Top Layer w10: v1(1875,1500) 1879.44,1500 1879.72,1500 1889.86,1489.86 1910,1469.72 1910.43,1469.29 U4.25
  Top Layer w20: 1889.86,1489.86 1896.93,1489.86 1910,1476.79 1910,1469.72 U4.25@1910,1440
  Top Layer w30: v1@1874.61,1535 1874.61,1500.39 v1(1875,1500) ; v1@1879.44,1500 v1@1886.4,1493.04
  Bottom Layer w30: v1(1875,1535) v1(1875,1500) 1905.47,1469.53 1905.47,1207.36 1705,1006.89 1705,704.65 1824.65,585 2174.06,585 2255,504.06 J6.2
DIR_A3979: R12.1 U2.25 | length 702.2
  Top Layer w10: U2.25 636.77,1508.23 786.69,1358.31 906.69,1358.31 930.47,1334.53 979.53,1334.53 v1(975,1330) ; v1(1070,1425) R12.1 R12.1@1160,1425
  Bottom Layer w10: v1(975,1330) v1(1070,1425)
FLOW_METER: R19.1 U2.22 | length 1260.8
  Top Layer w10: U2.22 713.54,1516.46 820.47,1409.53 961.87,1409.53 1033.31,1338.09 1033.31,1090.3 1056.69,1066.91 1056.69,963.68 1113.87,906.51 1275.25,906.51 1345,836.76 R19.1
GND1: C1.2 C16.2 C17.2 C21.2 D4.2 HS1.1 HS1.2 J3.4 J4.4 J5.4 LED1.1 LK1.1 LK2.1 LK3.1 U4.21 U4.29 | length 1543.8
  Top Layer w10: U4.29@2012.79,1332.79 2012.79,1357.79 U4.21
  Top Layer w20: v1(1300,3050) LED1.1 ; v1(1765,1970) 1767.05,1972.05 C16.2 1897.05,1972.05 v1(1900,1975) ; v1(1870,1285) 1905,1285 v1(1945,1325) ; v1(1870,1325) v1(1945,1325) ; v1(1945,1285) 1960,1285 U4.29 ; v1(1945,1365) 1960,1365 1972.5,1352.5 U4.29 ; v1(1985,1285) 2000,1300 U4.29@2000,1305 ; v1(1985,1365) 2000,1350 U4.29@2000,1345 ; v1(2020,1285) U4.29@2000,1305 ; v1(2020,1365) 2012.79,1357.79 U4.29@2000,1345 ; C21.2 v1(2050,1655) ; v1(2125,1325) U4.29@2035,1325 ; v1(2130,1285) 2075,1285 U4.29@2035,1325 ; v1(2130,1360) 2070,1360 U4.29@2035,1325 ; v1(2185,1970) 2187.05,1972.05 C17.2 2312.95,1972.05 v1(2315,1970) ; D4.2 v1(2640,3075) ; v1(1945,1325) v1(1985,1325) U4.29 ; U4.29@2000,1305 U4.29 ; U4.29 U4.29@2000,1345 ; U4.29 v1(2020,1325) U4.29@2035,1325
  Bottom Layer w20: LK2.1 1750,1955 v1(1765,1970)
GND2: C2.2 C3.2 C4.2 C6.2 C7.2 C8.2 C9.2 C10.2 C11.2 C12.2 C13.2 C14.2 C15.2 C20.2 C24.2 C25.2 C26.2 C27.2 D5.2 D6.2 J1.3 J2.5 LED2.1 LK1.2 P1.3 P2.4 R4.2 R5.2 R13.2 R30.2 R31.2 R32.2 R35.3 R36.2 R38.2 R41.2 R42.2 R49.2 R54.2 U1.3 U1.7 U1.9 U2.8 U2.19 U3.2 U3.5 U4.7 U4.26 Z1.2 | length 2837.9
  Top Layer w10: U2.8 739.13,1215.87 v1(740,1215) ; U2.19 790.31,1629.69 805,1644.38 805,1665 810,1670 v1(855,1670) ; v1(1825,1275) 1825,1325 1884.84,1384.84 U4.26 ; U4.7 1987.2,1147.8 v1(1990,1145)
  Top Layer w20: R32.2 v1(175,1595) ; R31.2 v1(175,2190) ; C14.2 v1(250,1595) ; C13.2 v1(250,2190) ; v1(300,740) 300.08,739.92 Z1.2 ; LED2.1 v1(350,2725) ; v1(635,2820) C26.2 ; v1(635,2880) R49.2 ; v1(655,920) 656.5,918.5 C10.2 ; C12.2 v1(855,1725) ; C9.2 843.5,918.5 v1(845,920) ; v1(850,2395) D6.2 ; v1(855,2185) 857.48,2182.52 C4.2 857.48,2062.52 v1(860,2060) ; v1(910,2525) U1.3 ; v1(925,2815) C27.2 ; v1(925,2875) R54.2 ; v1(975,2275) C6.2 ; R13.2 v1(1025,1705) ; v1(1040,1975) U3.2 ; v1(1050,2145) R4.2 ; v1(1075,2545) U1.9 ; v1(1100,1650) C7.2 ; v1(1105,1500) C8.2 ; v1(1115,2280) 1116.54,2281.54 R5.2 ; U1.7 v1(1245,2575) ; U3.5 v1(1365,1875) ; C15.2 v1(1400,2140) ; v1(1415,2320) 1417.48,2317.52 C3.2 1537.52,2317.52 v1(1540,2320) ; R30.2 v1(1500,2190) ; R36.2 v1(1625,1680) ; v1(1795,965) R38.2 ; v1(1855,965) C20.2 ; v1(1860,2320) 1862.48,2317.52 C2.2 1982.48,2317.52 v1(1985,2315) ; v1(1915,970) R41.2 ; v1(1975,965) C24.2 ; v1(2055,965) C25.2 ; v1(2115,970) R42.2 ; D5.2 v1(2300,2350)
  Bottom Layer w10: 1790,1140 1825,1175 v1(1825,1275)
GND3: C22.2 LK2.2 R39.1 | length 50.6
  Top Layer w20: v1(1445,1060) 1493.5,1060 C22.2
GND4: C23.2 LK3.2 R40.1 | length 50.6
  Top Layer w20: C23.2 2563.5,1058.5 v1(2565,1060)
GREEN: J6.4 U4.11 | length 1127.7
  Top Layer w20: 2089.56,1155.44 U4.11
  Top Layer w30: 2090.66,1161.74 2114.1,1138.31 2146.84,1138.31 2206.69,1078.46 2206.69,800.47 2555,452.17 J6.4
GREEN_LED: R27.1 U2.12 | length 785.6
  Top Layer w10: R27.1@245,1675 385,1675 630,1430 691.39,1430 779.78,1341.61 823.39,1341.61 841.49,1323.51 U2.12
M_0: R24.1 U2.4 | length 1019
  Top Layer w10: R24.1@385,2080 385,2035 v1(410,2010) ; v1(410,1690) v1(410,1940) ; v1(480,1465) 496.39,1465 558.09,1403.31 581.28,1403.31 596.39,1388.2 598.2,1388.2 636.77,1349.62 U2.4
  Bottom Layer w10: v1(410,1690) 415,1685 415,1620 359.53,1564.53 359.53,1509.45 403.98,1465 v1(480,1465) ; v1(410,1940) v1(410,2010)
M_1: R29.1 U2.5 | length 461.4
  Top Layer w10: R29.1@385,1475 v1(385,1520) ; v1(480,1505) 565,1420 590,1420 662.36,1347.64 U2.5
  Bottom Layer w10: v1(385,1520) 400,1505 v1(480,1505)
MCLR: P1.1 R6.2 U2.1 | length 760.5
  Top Layer w10: v1(480,1350) 490.08,1339.92 550,1339.92 560,1329.92 U2.1 ; P1.1 500,1770 516.54,1753.46 R6.2
  Bottom Layer w10: v1(480,1350) 480,1353.98 505.47,1379.45 505.47,1526.22 466.69,1565 466.69,1710.67 470.47,1714.45 470.47,1745.47 500,1775 P1.1
MS_1: U2.6 U4.13 | length 3258.5
  Top Layer w10: U2.6 687.95,1184.64 665,1161.69 518.09,1161.69 438.31,1081.91 438.31,928.09 544.7,821.69 948.09,821.69 1005,878.61 v1(1005,945) ; v1(1175,995) 1190,980 1660,980 1830.47,809.53 2140.47,809.53 v1(2150,800) ; U4.13 2140.74,1245.74 2149.12,1254.12 2185.88,1254.12 2285,1155 2315,1155 v1(2320,1160) ; v1(2275,800) 2280,805 2280,1040 v1(2320,1080)
  Bottom Layer w10: v1(1005,945) 1059.06,945 1114.53,1000.47 1169.53,1000.47 v1(1175,995) ; v1(2150,800) v1(2275,800) ; v1(2320,1080) v1(2320,1160)
MS_2: U2.7 U4.12 | length 3029.2
  Top Layer w10: U2.7 713.54,1168.54 690,1145 525,1145 455,1075 455,935 551.61,838.39 941.17,838.39 965,862.21 v1(965,965) ; v1(1175,1030) 1185,1030 1215,1000 1663.61,1000 1828.61,835 v1(2150,835) ; 2115.15,1175 2125.15,1165 2190,1165 2250,1105 v1(2250,850)
  Bottom Layer w10: v1(965,965) 970.47,970.47 1060.92,970.47 1120.45,1030 v1(1175,1030) ; v1(2150,835) 2235,835 v1(2250,850)
NetC5_1: C5.1 C6.1 U1.4 | length 164.2
  Top Layer w7.87: U1.4 975.51,2385.51 976.02,2385 C5.1@1050,2385
NetC5_2: C5.2 R4.1 | length 53.5
  Top Layer w10: R4.1@1050,2265 C5.2
NetC7_1: C7.1 R11.2 U4.19 | length 1446.9
  Top Layer w7.87: 2066.28,1496.36 2079.33,1509.42
  Top Layer w10: C7.1@1223.46,1646.54 R11.2 1340,1575 1440,1675 1550,1675 1720,1845 1916.39,1845 1918.09,1843.31 2041.69,1843.31 v1(2075,1810) ; U4.19 2066.69,1442.56 2066.69,1495.27 2080.39,1508.98 v1@2080.39,1673.44 ; v1(2076.72,1676.72) v1@2080,1673.44
  Bottom Layer w10: v1(2075,1810) 2075,1678.44 v1(2076.72,1676.72)
NetC8_1: C8.1 R12.2 U4.3 | length 1264.4
  Top Layer w10: R12.2@1215,1425 R12.2 ; C8.1@1223.46,1498.46 R12.2 ; v1(1275,1350) 1240,1315 1240,1070 1290,1020 1555,1020 1658.31,1123.31 1827.75,1123.31 1884.84,1180.4 U4.3 ; v1(1275,1425) R12.2
  Bottom Layer w10: v1(1275,1350) v1(1275,1425)
NetC9_1: C9.1 R14.1 X1.1 | length 310.9
  Top Layer w10: R14.1@885,1175 885,1115 915,1085 X1.1@915,1025 ; C9.1 X1.1@906.5,1023.5
NetC10_1: C10.1 U2.9 X1.2 | length 555.3
  Top Layer w10: C10.1 X1.2@593.5,1016.5 ; X1.2@595,1025 745,1025 765,1045 765,1203.22 765.47,1203.7 765.47,1279.25 U2.9
NetC13_1: C13.1 P2.7 R24.2 R31.1 | length 240
  Top Layer w10: P2.7 R24.2@315,2075
NetC14_1: C14.1 P2.1 R29.2 R32.1 | length 243
  Top Layer w10: P2.1@78.5,1478.5 C14.1 R29.2@321.5,1478.5
NetC18_2: C18.2 U4.22 | length 93
  Top Layer w10: U4.22 C18.2@1987.2,1532.8
NetC19_1: C19.1 U4.24 | length 98.9
  Top Layer w10: C19.1@1915,1530 1915,1505 1936.02,1483.98 U4.24
NetC19_2: C19.2 U4.23 | length 184.1
  Top Layer w10: C19.2@1920,1595 1940,1595 1950,1585 1950,1505 1961.61,1493.39 U4.23
NetC20_1: C20.1 R37.2 R38.1 U4.5 | length 320.3
  Top Layer w10: R37.2@1735,1080 1855,1080 1855,1100 1863,1108 1922.75,1108 1922.87,1107.87 ; 1921.9,1107.87 1922.87,1107.87 ; U4.5 1936.02,1119.9 1924,1107.87 1922.87,1107.87
NetC21_1: C21.1 U4.20 | length 95
  Top Layer w10: U4.20 2038.38,1483.38 2050,1495 C21.1@2050,1530
NetC22_1: C22.1 R39.2 U4.1 | length 460.2
  Top Layer w30: R39.2 1560,1125 1585,1150 1735,1150 1795,1210 U4.1@1830,1210
NetC23_1: C23.1 R40.2 U4.14 | length 474.9
  Top Layer w30: U4.14@2169.43,1210 2185,1210 2275,1120 2600,1120 R40.2
NetC24_1: C24.1 R41.1 U4.6 | length 202.5
  Top Layer w10: R41.1@1915,1080 1920,1075 1975,1075 C24.1 1975,1115 1961.61,1128.39 U4.6
NetC25_1: C25.1 R42.1 U4.9 | length 203.8
  Top Layer w10: U4.9 2038.38,1143.01 2055,1126.39 C25.1 2055,1075 2110,1075 R42.1@2115,1080
NetC26_1: C26.1 R45.2 R47.2 R49.1 SW1.3 | length 400.7
  Top Layer w10: SW1.3 R45.2 726.54,3008.46 740,2995 740,2880 745,2875 C26.1@745,2820 ; R49.1 R47.2@805,2880
NetC27_1: C27.1 R52.2 R53.2 R54.1 SW1.6 | length 383.1
  Top Layer w10: R52.2 SW1.6@1000,3115 ; R52.2@1005,3010 1035,3010 1043.46,3001.54 R54.1 R53.2@1095,2875 ; C27.1 R54.1@1041.5,2871.5
NetD1_1: D1.1 D3.1 | length 405.1
  Top Layer w50: D3.1 2655,3325 2714.45,3265.55 D1.1
NetD6_1: D6.1 L1.1 U1.1 | length 383.8
  Top Layer w50: L1.1@600,2645 D6.1 905,2645 925,2625 U1.1
NetJ1_1: J1.1 R8.2 R9.2 | length 349.9
  Top Layer w10: R8.2@411.54,546.54 R9.2 490,455 550,395 J1.1
NetJ1_2: J1.2 R7.2 R10.2 | length 345.8
  Top Layer w20: R7.2@570,545 640,545 R10.2@650,535 ; R10.2 650,453.7 700,403.7 J1.2
NetJ2_1: J2.1 R17.2 R18.2 | length 328
  Top Layer w10: R17.2@1145,555.59 R18.2 1205,441.65 1175,411.65 J2.1
NetJ2_2: J2.2 R16.2 R19.2 | length 347.9
  Top Layer w10: J2.2 1325,460 1358.46,493.46 R16.2@1358.46,540.59 ; R19.2 1345,589.06 1355,579.06 1355,544.06 R16.2@1358.46,540.59 ; R16.2 R16.2@1358.46,540.59
NetJ2_3: J2.3 R15.2 R20.2 | length 340.3
  Top Layer w10: J2.3 1475,460 1498.46,483.46 R15.2 1498.46,575.59 1485,589.06 R20.2
NetJ2_4: J2.4 R21.2 | length 325
  Top Layer w10: J2.4 R21.2
NetLED1_2: LED1.2 R1.2 | length 81.5
  Top Layer w10: LED1.2 R1.2@1300,3265
NetLED2_2: LED2.2 R2.2 | length 76.5
  Top Layer w10: R2.2 LED2.2@350,2585
NetP2_2: P2.2 R26.2 | length 304.9
  Top Layer w10: P2.2 125,1625 305,1625 315,1615 R26.2@315,1575
NetP2_3: P2.3 R27.2 | length 96.5
  Top Layer w10: P2.3@80,1675 R27.2
NetP2_5: P2.5 R28.2 | length 96.5
  Top Layer w10: P2.5@80,1875 R28.2
NetP2_6: P2.6 R25.2 | length 91.5
  Top Layer w10: P2.6@85,1975 R25.2
NetR3_2: R3.2 R5.1 U1.5 | length 159.4
  Top Layer w10: U1.5 1174.49,2445.51 1185,2435 R5.1@1185,2320
NetR14_2: R14.2 U2.10 | length 115.2
  Top Layer w10: U2.10 790.31,1234.69 815,1210 R14.2@815,1175
NetR33_2: R33.2 R36.1 U4.16 | length 1206.1
  Top Layer w10: R33.2@1560,1560 1710,1560 1760,1610 1760,1805 1780,1825 1875,1825 1935.35,1764.65 2139.65,1764.65 v1(2155,1780) ; U4.16 2140.74,1481.11 2166.69,1507.06 2166.69,1596.91 2155,1608.61 v1(2155,1675)
  Bottom Layer w10: v1(2155,1675) v1(2155,1780)
NetR34_2: R34.2 R35.1 | length 86.5
  Top Layer w10: R34.2 R35.1@1191.54,1288.46
NetR35_2: R35.2 U4.8 | length 1538.1
  Top Layer w10: R35.2@1285,1190 1285,1095 v1(1330,1050) ; v1(1330,935) 1605,935 1775,765 2051.69,765 v1(2065,778.31) ; U4.8 2012.79,1158.23 2015.47,1155.55 2015.47,1133.98 2015,1133.5 v1(2015,887.13)
  Bottom Layer w10: v1(1330,935) v1(1330,1050) ; v1(2015,887.13) 2015,828.31 v1(2065,778.31)
NetR43_2: R43.2 R44.1 SW1.1 SW1.11 | length 606.8
  Top Layer w10: R44.1@600,2940 565,2940 550,2955 550,2990 531.54,3008.46 R43.2 SW1.1 500,3225 600,3325 SW1.11
NetR44_2: R44.2 R45.1 SW1.2 SW1.10 | length 612.7
  Top Layer w10: R45.1@700,2940 665,2940 650,2955 650,3000 641.54,3008.46 R44.2 SW1.2 600,3225 700,3325 SW1.10
NetR47_1: R47.1 U2.2 | length 2274.3
  Top Layer w10: v1(340,1940) 345,1935 v1(345,1705) ; v1(340,2165) 340,2245 265,2320 265,2740 300,2775 790,2775 805,2790 R47.1 R47.1@805,2815 ; v1(480,1390) 510,1390 535,1365 560,1365 585,1340 U2.2@585,1310 ; U2.2 U2.2@585.59,1310
  Bottom Layer w10: v1(340,1940) v1(340,2165) ; v1(345,1705) 345,1697.83 367.83,1675 367.83,1637.83 326.14,1596.14 326.14,1493.86 430,1390 v1(480,1390)
NetR50_2: R50.2 R51.1 SW1.4 SW1.8 | length 609.7
  Top Layer w10: SW1.8 900,3325 800,3225 SW1.4 R50.2 836.54,3008.46 850,2995 850,2960 865,2945 R51.1@905,2945
NetR51_2: R51.2 R52.1 SW1.5 SW1.7 | length 609.7
  Top Layer w10: R52.1@1000,2940 965,2940 945,2960 945,3000 936.54,3008.46 R51.2 SW1.5 900,3225 1000,3325 SW1.7
NetR53_1: R53.1 U2.3 | length 2565.3
  Top Layer w10: v1(375,1940) 380,1940 v1(380,1725) ; v1(375,2165) 375,2240 285,2330 285,2725 318.31,2758.31 1093.31,2758.31 1105,2770 R53.1 R53.1@1105,2815 ; v1(480,1430) 507.79,1430 551.17,1386.61 568.39,1386.61 610,1345 ; U2.3 611.18,1345
  Bottom Layer w10: v1(375,1940) v1(375,2165) ; v1(380,1725) 385,1720 385,1701.5 384.53,1701.02 384.53,1624.53 342.83,1582.83 342.83,1502.53 415.37,1430 v1(480,1430)
PGC: P1.5 U2.27 | length 498.6
  Top Layer w10: U2.27 585.59,1610.59 650,1675 v1(690,1675) ; v1(690,1760) 835,1760 P1.5
  Bottom Layer w10: v1(690,1675) v1(690,1760)
PGD: P1.4 U2.28 | length 514.1
  Top Layer w10: U2.28 560,1630 625,1695 633.98,1695 v1(633.5,1694.53) ; v1(635,1760) 655,1780 655,1855 680,1880 745,1880 P1.4
  Bottom Layer w10: v1(633.5,1694.53) 635,1696.02 v1(635,1760)
RED: J6.3 U4.4 | length 1519.4
  Top Layer w10: v1(1910,1160) v1@1910.43,1160.43
  Top Layer w20: v1@1910.43,1135.43 1910.43,1160.43 U4.4
  Bottom Layer w30: v1(1910,1160) v1(1910,1134) 1745,969 1745,730.84 1841.79,634.06 2255.94,634.06 2405,485 J6.3
RED_LED: R28.1 U2.11 | length 957.9
  Top Layer w10: R28.1@245,1875 280,1875 300,1855 300,1715 v1(295,1710) ; v1(335,1645) 348.31,1658.31 378.09,1658.31 623.09,1413.31 684.48,1413.31 772.86,1324.92 810.08,1324.92 815.9,1319.1 U2.11
  Bottom Layer w10: v1(295,1710) 335,1670 v1(335,1645)
RESET_A3979: R13.1 U2.26 U4.17 | length 2238.5
  Top Layer w10: U2.26 611.18,1498.82 635,1475 v1(630,1475) ; v1(950,1500) 980,1530 1000,1530 1025,1555 1025,1590 1060,1590 1070,1600 1070,1685 1085,1700 1551.39,1700 1713.09,1861.69 1923.31,1861.69 1925,1860 2061.02,1860 2100.47,1820.55 2100.47,1809.53 v1(2115,1795) ; v1(2115,1680) 2115,1625 2150,1590 2150,1513.98 2115.15,1479.13 U4.17
  Bottom Layer w10: v1(630,1475) 925,1475 v1(950,1500) ; v1(2115,1680) v1(2115,1795)
RX: U2.18 U3.1 | length 651.5
  Top Layer w10: U2.18 815.9,1610.9 849.53,1644.53 865.55,1644.53 950,1728.98 950,1985 990,2025 U3.1@1100,2025
SCL: R21.1 U2.14 | length 1162.5
  Top Layer w10: U2.14 892.67,1239.02 900,1231.69 943.31,1231.69 990,1185 990,1190 v1(990.51,1190.51) ; v1(1075.93,1184.25) 1081.77,1184.25 1108.39,1157.64 1108.39,960 1128.39,940 1288.98,940 1319.45,909.53 1561.94,909.53 1625,846.47 R21.1
  Bottom Layer w10: v1(990.51,1190.51) 1069.67,1190.51 v1(1075.93,1184.25)
SDA: R20.1 U2.15 | length 1238.9
  Top Layer w10: U2.15 892.67,1502.33 1050,1345 1050,1097.21 1075,1072.21 1075,968.98 1120.78,923.2 1282.17,923.2 1312.53,892.83 1437.33,892.83 1485,845.17 R20.1 R20.1@1485,739.06
SENSOR: R10.1 U2.23 Z1.1 | length 1561.2
  Top Layer w10: Z1.1@525,740 625,740 650,715 ; R10.1 650,715 ; U2.23 687.95,1512.05 807.17,1392.83 954.95,1392.83 1016.61,1331.17 1016.61,1083.39 1040,1060 1040,890 890,740 675,740 650,715
SLEEP: U2.21 U4.27 | length 1365.2
  Top Layer w10: U2.21 739.13,1520.87 825,1435 v1(920,1435) ; v1(1005,1435) 1060,1380 1425,1380 1540,1495 1713.11,1495 1823.11,1385 1850,1385 1859.25,1394.25 U4.27
  Bottom Layer w10: v1(920,1435) v1(1005,1435)
STEP_A3979: R11.1 U2.24 | length 756
  Top Layer w10: U2.24 662.36,1514.03 801.39,1375 935,1375 v1(950,1360) ; v1(1030,1495) 1030,1525 1080,1575 R11.1@1155,1575
  Bottom Layer w10: v1(950,1360) 999.53,1409.53 1015.55,1409.53 1030.47,1424.45 1030.47,1446.02 1030,1446.5 v1(1030,1495)
TX: U2.17 U3.4 | length 464.5
  Top Layer w10: U2.17 841.49,1607.88 858.61,1625 869.63,1625 966.69,1722.06 966.69,1746.69 995,1775 1025,1775 1045,1795 1045,1860 1060,1875 U3.4@1100,1875
TX_EN: U2.16 U3.3 | length 607.2
  Top Layer w10: U2.16 867.08,1600.39 875,1608.31 878.31,1608.31 983.39,1713.39 983.39,1739.78 1001.91,1758.31 1031.91,1758.31 1061.69,1788.09 1061.69,1821.69 1080,1840 1155,1840 1175,1860 1175,1910 1160,1925 U3.3@1110,1925
V+POWER: C1.1 C16.1 C17.1 C18.1 D2.2 D3.2 D4.1 R1.1 R9.1 R18.1 U4.15 U4.28 | length 9130.3
  Top Layer w10: R1.1 1531.54,3333.46 1740,3125 C1.1
  Top Layer w20: R9.1 511.54,613.46 530,595 530,485 630,385 630,225 675,180 1189.45,180 1250,240.55 ; R18.1 1236.54,622.52 1250,609.06 1250,240.55 ; C18.1 1985,1727.95 1985,1730 ; 2440,1730 2640,1730 2685,1685 2685,285 2585,185 1305.55,185 1250,240.55
  Top Layer w50: 1820.56,1440 1820,1440 1820,1475 1795,1500 1795,1580 1825,1610 C16.1 1985,1727.95 C17.1@2247.05,1727.95 ; C1.1 1850,3225 1950,3325 D3.2 ; 2179.43,1440 2180,1440 2250,1510 C17.1 ; C17.1@2250,1730 2440,1730 2440,2170 2540.55,2270.55 D2.2 ; D3.2@2260,3325 2260,2970 2310,2920 2515,2920 2540,2895 D2.2@2540,2780
VCC: C2.1 C3.1 D2.1 D5.1 U1.8 | length 1411.6
  Top Layer w50: U1.8@1172.52,2632.48 C3.1 ; C3.1@1480,2630 2065,2630 2155,2540 2300,2540 D5.1 2300,2640 2259.45,2680.55 D2.1
VIN: D1.2 J3.1 J4.1 J5.1 | length 2730.5
  Top Layer w50: D1.2 2950.55,2984.45 3010,2925 3010,2290 ; J4.1@2879.02,1553.31 J4.1@2880,1553.31 ; J3.1 2965,775 3010,820 3010,1535 ; J4.1 3010,1535 ; J5.1 2995,2275 3010,2290 ; 3010,1535 3010,2290
pads on no net: P1.6 U1.2 U1.6 U2.13 U4.2

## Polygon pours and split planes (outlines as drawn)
GND3 on Bottom Layer "Bot - GND3" (solid, remove dead copper, pour order 11): 1675,1850 1825,1850 1825,1625 1775,1625 1775,1500 1500,1500 1500,1025 1350,1025 1350,1650 1675,1650
GND4 on Bottom Layer "Bot - GND4" (solid, pour order 12): 2250,1850 2250,1625 2500,1625 2500,1025 2675,1025 2675,1850
GND1 on Bottom Layer "Bot - GND1" (solid, remove dead copper, pour order 13): 3300,3500 1225,3500 1225,2775 2450,2775 2450,2275 1950,2275 1950,2075 1675,2075 1675,1875 1875,1875 1875,1600 1800,1600 1800,1475 1525,1475 1525,1175 2475,1175 2475,1600 2200,1600 2200,1875 2700,1875 2700,650 3300,650
GND1 on Bottom Layer "Bot - GND1a" (solid, pour order 14): 1950,2275 1950,2075 1675,2075 1675,1875 2425,1875 2425,2275
GND1 on Bottom Layer "Bot - GND1-HSK" (solid, remove dead copper, pour order 15): 1525,1475 1525,1175 2475,1175 2475,1475
GND2 on Bottom Layer "Bot - GND2" (solid, remove dead copper, pour order 16): 50,3500 1200,3500 1200,2750 2425,2750 2425,2300 1900,2300 1900,2100 1650,2100 1650,1675 1325,1675 1325,1000 1525,1000 1525,1150 2475,1150 2475,1000 2675,1000 2675,625 3300,625 3300,25 50,25
GND3 on Bottom Layer "Bot - GND3a" (solid, pour order 17): 1675,1825 1825,1825 1825,1700 1675,1700
GND4 on Bottom Layer "Bot - GND4a" (solid, pour order 18): 2250,1825 2425,1825 2425,1750 2250,1750
GND2 on Bottom Layer "Bot - GND2a" (solid, pour order 19): 1900,2300 1900,2100 1825,2100 1825,2300
GND1 on Top Layer "Top - GND1-HSK" (solid, remove dead copper, pour order 22): 2115,1385 2115,1270 2205,1270 2220,1255 2300,1175 2475,1175 2475,1600 2300,1600 2300,1385

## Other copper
Top Layer:
  text "TOP" at 85,1010 h78.74 r90
Bottom Layer:
  text "BOTTOM" at 87.2,1219.84 h78.74 r90

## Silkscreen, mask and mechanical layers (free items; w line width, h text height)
Top Overlay:
  lines w5: 570,510 590,490 695.28,490 ; 1080,2290 1095,2275
Bottom Overlay:
  circle w7.87: c1426,2980.73 r68.9
  region: 835.55,2271.26 847.08,2243.42 874.92,2231.89 1396.57,2231.89 1424.41,2243.42 1435.94,2271.26 1435.94,2359.84 1424.41,2387.68 1396.57,2399.21 874.92,2399.21 847.08,2387.68 835.55,2359.84
  lines w11.81: 976.93,2678.5 976.93,2503.5 1126.93,2503.5 ; 976.93,2678.7 1126.93,2678.7 1276.93,2678.7 1426.93,2678.7 ; 1126.93,2678.5 1126.93,2503.5 ; 1276.93,2678.5 1276.93,2503.5 ; 1426.93,2678.5 1426.93,2503.5 1276.93,2503.5 ; 1126.93,2503.5 1276.93,2503.5
  text "C    2014" at 1449.41,2950.83 h78.74
  text "AGRIGEL" at 2175,2920 h137.8
  text ".PCB_TITLE" at 2168.82,2796.93 h100
  text ".Version" at 2168.82,2668.98 h100
  text "MOD:" at 1675,2565 h88.58
  text "C" at 1097.01,2542.52 h137.8
  text "B" at 1238.74,2542.52 h137.8
  text "A" at 1396.22,2542.52 h137.8
  text "ISSUE:" at 1720,2275 h88.58
Board:
  the board outline again, w2
Mechanical 15:
  circle w1: c196.85,3346.46 r78.74
  circle w1: c3149.61,3346.46 r78.74
  circle w1: c3149.61,196.85 r78.74
  circle w1: c196.85,196.85 r78.74
  lines w2: 0,196.85 393.7,196.85 ; 0,3346.46 393.7,3346.46 ; 25,25 3325,3525 ; 25,3525 3325,25 ; 196.85,0 196.85,393.7 ; 196.85,3149.61 196.85,3543.31 ; 2952.76,196.85 3346.46,196.85 ; 2952.76,3346.46 3346.46,3346.46 ; 3149.61,0 3149.61,393.7 ; 3149.61,3149.61 3149.61,3543.31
